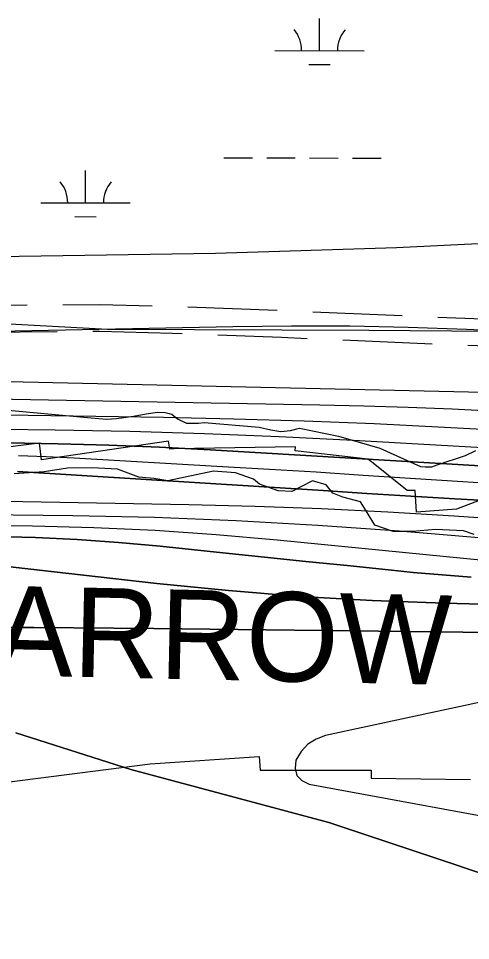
# Model space of a CAD drawing. Extents: x 3219052 to 3256913, y 800770 to 826146.
# Drawn here: x 3230665 to 3231171, y 817204 to 818235 of the extents above; entities that cross this region are included whole.
import ezdxf

# ---------------------------------------------------------------- set-up
doc = ezdxf.new("R2010")
doc.units = 0
for name, color, linetype in [('V-RIVR-EDGE', 7, 'Continuous'), ('V-ROAD-CNTR', 7, 'Continuous'), ('V-RRAP-RVMT', 7, 'Continuous'), ('V-RRAP-RVMT-IDEN', 7, 'Continuous'), ('V-SITE-VEGE', 7, 'Continuous'), ('V-TOPO-DPTH', 7, 'Continuous'), ('V-TOPO-MAJR', 7, 'Continuous'), ('V-TOPO-MINR', 7, 'Continuous'), ('V-TOPO-WATR', 7, 'Continuous'), ('V-WETL-SWMP', 7, 'Continuous')]:
    doc.layers.add(name, color=color, linetype=linetype)

msp = doc.modelspace()

# ---------------------------------------------------------------- linework, layer by layer
at = {"layer": 'V-RIVR-EDGE'}
msp.add_lwpolyline([(3231174.7, 817657.9), (3231162.6, 817661.9), (3231131.3, 817663.3), (3231105.6, 817661.1), (3231083.9, 817661.2), (3231063.5, 817668.2), (3231053.9, 817684.3), (3231047.5, 817694.3), (3231027.5, 817699.6), (3231016.6, 817704), (3231008.8, 817713.5), (3230993.6, 817717.9), (3230970.5, 817705.8), (3230955.3, 817706.7), (3230934.5, 817714.2), (3230927.5, 817719.8), (3230907.6, 817726.8), (3230882.8, 817728.6), (3230831.9, 817717.9), (3230816.3, 817720.5), (3230799.3, 817721.9), (3230775.4, 817731.1), (3230747.2, 817732.5), (3230719.4, 817732.1), (3230693.3, 817727.8), (3230659.8, 817725.7)], dxfattribs=at)
at = {"layer": 'V-ROAD-CNTR'}
for p, q in [((3230954.2, 817908.4), (3230854.2, 817912)), ((3231094, 817902.3), (3230994.1, 817906.7)), ((3231233.9, 817897), (3231134, 817900.6)), ((3231127.6, 817870.8), (3231027.7, 817875.2))]:
    msp.add_line(p, q, dxfattribs=at)
for points in [[(3230674.3, 817914.3), (3230625.8, 817914), (3230574.3, 817915.9)], [(3230814.3, 817913.3), (3230755.6, 817914.8), (3230714.3, 817914.5)], [(3230585.8, 817897.4), (3230764.2, 817887.5), (3231056.9, 817886.3), (3231334.5, 817884.2), (3231463.1, 817879.2), (3231574.9, 817868.7), (3231737.2, 817863.7), (3231809.8, 817860.7), (3231876.6, 817848.6), (3231928.6, 817844.9), (3231999.5, 817846.5), (3232100, 817847.1), (3232247.3, 817862.1)], [(3230707.9, 817884.5), (3230625.3, 817884), (3230607.9, 817884.6)], [(3230847.9, 817882.3), (3230837.1, 817882.7), (3230755.3, 817884.8), (3230747.9, 817884.8)], [(3230987.8, 817876.9), (3230958.9, 817878.2), (3230887.8, 817880.8)], [(3231267.5, 817865.4), (3231261, 817866), (3231167.6, 817869.3)]]:
    msp.add_lwpolyline(points, dxfattribs=at)
at = {"layer": 'V-RRAP-RVMT'}
for points in [[(3230838.7, 817753.6), (3230834.2, 817753.3), (3230832.5, 817762.2), (3230690.4, 817741.2), (3230688.1, 817759.9), (3230631.6, 817752.8), (3230631.4, 817756.7), (3230542.5, 817770.8), (3230540.4, 817762.9), (3230428.9, 817767.3), (3230427.6, 817772.6), (3230297.1, 817753.7), (3230295.9, 817762.3), (3230155.1, 817747.8), (3230155.7, 817741.9), (3230083.5, 817714.2)], [(3231109.9, 817682.7), (3231108.6, 817707), (3231099.5, 817706.9), (3231056.1, 817742.2), (3230974.2, 817751.3), (3230974.5, 817755.9), (3230838.7, 817753.6)], [(3232165.3, 817719.6), (3232052.4, 817690.3), (3232049.5, 817700.3), (3231980.9, 817683.5), (3231976.7, 817687.4), (3231906.8, 817683.8), (3231878.5, 817676.5), (3231876.3, 817681.2), (3231770.8, 817693.1), (3231760.5, 817688.7), (3231757.8, 817692.6), (3231630.9, 817713.5), (3231629.3, 817716.7), (3231617.5, 817713.7), (3231616, 817717.7), (3231480.4, 817738.6), (3231472, 817736.5), (3231470.7, 817739.2), (3231344.7, 817733.2), (3231342, 817738.9), (3231213.9, 817703.1), (3231211.6, 817707.9), (3231154.7, 817686.3), (3231109.9, 817682.7)], [(3230557.8, 817369), (3230812, 817401.2)], [(3230812, 817401.2), (3230933.9, 817409.6), (3230935, 817394.3), (3231059.4, 817394.2), (3231059.5, 817385.2), (3231170.6, 817383.9)]]:
    msp.add_lwpolyline(points, dxfattribs=at)
at = {"layer": 'V-SITE-VEGE'}
for p, q in [((3230613.9, 817800.7), (3230745.9, 817788.2)), ((3230807.6, 817792.7), (3230820.4, 817794.6)), ((3230820.4, 817794.6), (3230828.8, 817794.5)), ((3230828.8, 817794.5), (3230836.4, 817792.3)), ((3230745.9, 817788.2), (3230763, 817787)), ((3230763, 817787), (3230774.5, 817787.6)), ((3230774.5, 817787.6), (3230793.3, 817790.3)), ((3230793.3, 817790.3), (3230807.6, 817792.7)), ((3230836.4, 817792.3), (3230842.5, 817787.1)), ((3230842.5, 817787.1), (3230852.5, 817782.3)), ((3230852.5, 817782.3), (3230866, 817782.5)), ((3230866, 817782.5), (3230872.4, 817783.3)), ((3230872.4, 817783.3), (3230934.1, 817777.8)), ((3230934.1, 817777.8), (3230947.2, 817774.9)), ((3230947.2, 817774.9), (3230958.2, 817773)), ((3230958.2, 817773), (3230969, 817774.1)), ((3230969, 817774.1), (3230979.2, 817776.7)), ((3230979.2, 817776.7), (3231022.6, 817767.9)), ((3231022.6, 817767.9), (3231069.2, 817754.5)), ((3231069.2, 817754.5), (3231114.6, 817734)), ((3231165, 817746.2), (3231176.6, 817751.9)), ((3231133.1, 817735.8), (3231165, 817746.2)), ((3231114.6, 817734), (3231119.6, 817733.4)), ((3231119.6, 817733.4), (3231127.1, 817733.7)), ((3231127.1, 817733.7), (3231133.1, 817735.8))]:
    msp.add_line(p, q, dxfattribs=at)
at = {"layer": 'V-TOPO-DPTH'}
for points in [[(3230652.5, 817760.4), (3230709.1, 817759.4), (3230765.8, 817757.9), (3230822.4, 817755.5), (3230879, 817752.5), (3231288.3, 817728.2), (3231293.9, 817727.8), (3231299.4, 817727.5), (3231304.9, 817727.2), (3231310.5, 817726.9), (3231316, 817726.6), (3231321.6, 817726.4), (3231327.1, 817726.2), (3231332.6, 817726.1), (3231981, 817713.4), (3232007.9, 817713), (3232034.7, 817713), (3232061.6, 817713.4), (3232088.5, 817714.1), (3232573.7, 817730.8)], [(3230663.4, 817728.5), (3231005.5, 817707), (3231054.6, 817703.9), (3231103.7, 817700.9), (3231152.8, 817697.9), (3231201.9, 817695)], [(3231201.9, 817695), (3231152.8, 817697.9), (3231103.7, 817700.9), (3231054.6, 817703.9), (3231005.5, 817707), (3230663.4, 817728.5)], [(3232144.2, 817648.9), (3232056.2, 817644.3), (3232044.7, 817643.8), (3232033.3, 817643.4), (3232021.8, 817643.1), (3232010.3, 817642.9), (3231604.1, 817637.7), (3231553.6, 817637.4), (3231503, 817637.6), (3231452.5, 817638.6), (3231402, 817640.1), (3231382, 817640.9), (3231341.5, 817642.7), (3231301, 817644.8), (3231260.5, 817647.5), (3231220, 817650.6), (3231090.8, 817661.4), (3230999.6, 817668), (3230908.3, 817673.3), (3230817, 817676.7), (3230725.5, 817678.7), (3230592, 817680.3)], [(3232144.2, 817648.9), (3232056.2, 817644.3), (3232044.7, 817643.8), (3232033.3, 817643.4), (3232021.8, 817643.1), (3232010.3, 817642.9), (3231604.1, 817637.7), (3231553.6, 817637.4), (3231503, 817637.6), (3231452.5, 817638.6), (3231402, 817640.1), (3231382, 817640.9), (3231341.5, 817642.7), (3231301, 817644.8), (3231260.5, 817647.5), (3231220, 817650.6), (3231090.8, 817661.4), (3230999.6, 817668), (3230908.3, 817673.3), (3230817, 817676.7), (3230725.5, 817678.7), (3230592, 817680.3)], [(3230637, 817655.7), (3230683.6, 817654.5), (3230730.2, 817652.4), (3230776.7, 817649), (3230823.2, 817644.8), (3230893.5, 817637.4), (3230939.8, 817632.6), (3230986.1, 817627.8), (3231032.4, 817623.1), (3231078.6, 817618.3), (3231106.3, 817615.5), (3231138.8, 817612.6), (3231171.3, 817610.1)], [(3230637, 817655.7), (3230683.6, 817654.5), (3230730.2, 817652.4), (3230776.7, 817649), (3230823.2, 817644.8), (3230893.5, 817637.4), (3230939.8, 817632.6), (3230986.1, 817627.8), (3231032.4, 817623.1), (3231078.6, 817618.3), (3231106.3, 817615.5), (3231138.8, 817612.6), (3231171.3, 817610.1)], [(3232532.2, 817627.7), (3232109.1, 817594.8), (3232070.6, 817592.1), (3232032.1, 817589.6), (3231993.5, 817587.5), (3231954.9, 817585.7), (3231938.7, 817585), (3231891.9, 817583.3), (3231845.2, 817581.9), (3231798.4, 817581), (3231751.7, 817580.4), (3231350.5, 817577.1), (3231326.3, 817577), (3231302.1, 817577.1), (3231277.9, 817577.4), (3231253.7, 817577.9), (3231140.9, 817580.9), (3231060.4, 817584), (3230979.9, 817588.6), (3230899.6, 817595.2), (3230819.4, 817603.1), (3230576.3, 817630.5)], [(3230576.3, 817630.5), (3230819.4, 817603.1), (3230899.6, 817595.2), (3230979.9, 817588.6), (3231060.4, 817584), (3231140.9, 817580.9), (3231253.7, 817577.9), (3231277.9, 817577.4), (3231302.1, 817577.1), (3231326.3, 817577), (3231350.5, 817577.1), (3231751.7, 817580.4), (3231798.4, 817581), (3231845.2, 817581.9), (3231891.9, 817583.3), (3231938.7, 817585), (3231954.9, 817585.7), (3231993.5, 817587.5), (3232032.1, 817589.6), (3232070.6, 817592.1), (3232109.1, 817594.8), (3232532.2, 817627.7)], [(3232117.6, 817554.2), (3232046.1, 817551.8), (3232038.7, 817551.6), (3232031.3, 817551.4), (3232023.9, 817551.3), (3232016.5, 817551.2), (3231882.9, 817550.3), (3231808.7, 817549.9), (3231734.5, 817549.4), (3231660.3, 817549), (3231586.1, 817548.6), (3231380.7, 817547.5), (3231341.7, 817547.4), (3231302.6, 817547.4), (3231263.6, 817547.6), (3231224.6, 817548), (3230816.1, 817552.6), (3230771.4, 817553.1), (3230726.7, 817553.5), (3230682, 817553.7), (3230637.4, 817553.9)], [(3230637.4, 817553.9), (3230682, 817553.7), (3230726.7, 817553.5), (3230771.4, 817553.1), (3230816.1, 817552.6), (3231224.6, 817548), (3231263.6, 817547.6), (3231302.6, 817547.4), (3231341.7, 817547.4), (3231380.7, 817547.5), (3231586.1, 817548.6), (3231660.3, 817549), (3231734.5, 817549.4), (3231808.7, 817549.9), (3231882.9, 817550.3), (3232016.5, 817551.2), (3232023.9, 817551.3), (3232031.3, 817551.4), (3232038.7, 817551.6), (3232046.1, 817551.8), (3232117.6, 817554.2)], [(3230661.5, 817435.9), (3230790.5, 817395.1), (3231011.8, 817335.7), (3231308.3, 817236.8), (3231331.5, 817235), (3231354.8, 817233.4), (3231378, 817232), (3231401.3, 817230.8), (3231424.6, 817229.8), (3231447.9, 817229), (3231968, 817212.1), (3231996, 817211.2), (3232023.9, 817210.3), (3232051.9, 817209.5), (3232079.8, 817208.8), (3232271.6, 817203.6)], [(3232271.6, 817203.6), (3232079.8, 817208.8), (3232051.9, 817209.5), (3232023.9, 817210.3), (3231996, 817211.2), (3231968, 817212.1), (3231447.9, 817229), (3231424.6, 817229.8), (3231401.3, 817230.8), (3231378, 817232), (3231354.8, 817233.4), (3231331.5, 817235), (3231308.3, 817236.8), (3231011.8, 817335.7), (3230790.5, 817395.1), (3230661.5, 817435.9)]]:
    msp.add_lwpolyline(points, dxfattribs=at)
at = {"layer": 'V-TOPO-MAJR'}
for points in [[(3232140.7, 817751.4), (3232053.8, 817748.4), (3232044.7, 817748.1), (3232035.5, 817748), (3232026.3, 817748.1), (3232017.2, 817748.2), (3231924.9, 817750.7), (3231869.6, 817752.6), (3231814.3, 817754.9), (3231759.1, 817758), (3231703.9, 817761.6), (3231363.6, 817785.9), (3231330.9, 817788.1), (3231298.3, 817790.2), (3231265.6, 817792.1), (3231232.9, 817793.9), (3231199.5, 817795.6), (3231150, 817797.9), (3231100.6, 817799.9), (3231051.2, 817801.4), (3231001.7, 817802.5), (3230616.8, 817809.6)], [(3231234, 817481.3), (3231008.2, 817433), (3230997.6, 817428.9), (3230988.3, 817423.3), (3230981, 817415.1), (3230975.2, 817405.3), (3230974.4, 817396.1), (3230976.1, 817388.3), (3230981.7, 817382.7), (3230989.9, 817378.4), (3231271.7, 817326.7)]]:
    msp.add_lwpolyline(points, dxfattribs=at)
at = {"layer": 'V-TOPO-MINR'}
for points in [[(3232232.9, 817846.1), (3232057.3, 817846.3), (3232047.4, 817846.4), (3232037.6, 817846.5), (3232027.8, 817846.7), (3232017.9, 817847), (3231927.3, 817850.1), (3231872.2, 817852.1), (3231817.1, 817854.3), (3231762, 817856.9), (3231706.9, 817859.6), (3231352.8, 817878.3), (3231324.7, 817879.8), (3231296.6, 817881.2), (3231268.5, 817882.5), (3231240.5, 817883.8), (3231166, 817887.1), (3231100.7, 817889.4), (3231035.3, 817890.8), (3230970, 817891), (3230904.6, 817890.3), (3230585.5, 817883.9)], [(3232110.3, 817762), (3232091.7, 817761.5), (3232073, 817760.9), (3232042.3, 817759.8), (3232039, 817759.7), (3232035.7, 817759.6), (3232032.5, 817759.7), (3232029.2, 817759.7), (3231997.4, 817760.7), (3231978.3, 817761.4), (3231959.1, 817762.2), (3231940, 817763.4), (3231920.8, 817764.7), (3231335.4, 817809.3), (3231316.6, 817810.7), (3231297.9, 817811.9), (3231279.1, 817813), (3231260.3, 817814), (3231241.5, 817814.8), (3231222.7, 817815.5), (3231203.9, 817816.1), (3231185.1, 817816.6), (3230536.6, 817831.2)], [(3232208.9, 817742), (3232065.4, 817737), (3232050.3, 817736.6), (3232035.2, 817736.4), (3232020.2, 817736.4), (3232005.1, 817736.7), (3231842.5, 817740.7), (3231751.8, 817743.5), (3231661.1, 817747.1), (3231570.4, 817751.8), (3231479.8, 817757.2), (3231342.7, 817766.3), (3231320.7, 817767.7), (3231298.6, 817769), (3231276.6, 817770.3), (3231254.6, 817771.6), (3231141.5, 817777.7), (3231062.8, 817781.5), (3230984.2, 817784.7), (3230905.5, 817787), (3230826.8, 817788.7), (3230599.5, 817792.1)], [(3232365.5, 817735.5), (3232076.9, 817725.6), (3232056, 817725), (3232035, 817724.7), (3232014, 817724.8), (3231993, 817725), (3231596.9, 817733.9), (3231547.2, 817735.3), (3231497.6, 817737), (3231447.9, 817739.4), (3231398.3, 817742.1), (3231322.1, 817746.7), (3231310.5, 817747.4), (3231299, 817748.1), (3231287.5, 817748.8), (3231276, 817749.5), (3231039.7, 817763), (3230956.3, 817767.2), (3230872.8, 817770.6), (3230789.2, 817773), (3230705.7, 817774.6), (3230583.7, 817776.1)], [(3232573.7, 817730.8), (3232088.5, 817714.1), (3232061.6, 817713.4), (3232034.7, 817713), (3232007.9, 817713), (3231981, 817713.4), (3231332.6, 817726.1), (3231327.1, 817726.2), (3231321.6, 817726.4), (3231316, 817726.6), (3231310.5, 817726.9), (3231304.9, 817727.2), (3231299.4, 817727.5), (3231293.9, 817727.8), (3231288.3, 817728.2), (3230879, 817752.5), (3230822.4, 817755.5), (3230765.8, 817757.9), (3230709.1, 817759.4), (3230652.5, 817760.4)], [(3231184.9, 817715.3), (3231161.9, 817716.7), (3231102.8, 817720.6), (3231050.4, 817724), (3230997.9, 817727.4), (3230945.4, 817730.5), (3230892.8, 817733.6), (3230726.9, 817743.2), (3230695.7, 817744.7), (3230664.5, 817746)], [(3232125.1, 817658), (3232094.6, 817656.7), (3232045.9, 817654.2), (3232039.7, 817654), (3232033.5, 817653.7), (3232027.3, 817653.6), (3232021, 817653.5), (3231900.4, 817652.4), (3231833.9, 817652.2), (3231767.4, 817652.7), (3231700.9, 817654), (3231634.4, 817656), (3231357.4, 817666), (3231329, 817667.2), (3231300.5, 817668.5), (3231272, 817670.2), (3231243.6, 817672), (3231152.2, 817678.3), (3231078, 817682.8), (3231003.8, 817686.6), (3230929.6, 817689.2), (3230855.3, 817691.1), (3230607.3, 817695.6)], [(3232144.2, 817648.9), (3232056.2, 817644.3), (3232044.7, 817643.8), (3232033.3, 817643.4), (3232021.8, 817643.1), (3232010.3, 817642.9), (3231604.1, 817637.7), (3231553.6, 817637.4), (3231503, 817637.6), (3231452.5, 817638.6), (3231402, 817640.1), (3231382, 817640.9), (3231341.5, 817642.7), (3231301, 817644.8), (3231260.5, 817647.5), (3231220, 817650.6), (3231090.8, 817661.4), (3230999.6, 817668), (3230908.3, 817673.3), (3230817, 817676.7), (3230725.5, 817678.7), (3230592, 817680.3)], [(3231189.1, 817628.4), (3230954.2, 817651.7), (3230885.9, 817657.6), (3230817.5, 817662.4), (3230748.9, 817665.3), (3230680.4, 817667.1), (3230580.5, 817668.4)], [(3231171.3, 817610.1), (3231138.8, 817612.6), (3231106.3, 817615.5), (3231078.6, 817618.3), (3231032.4, 817623.1), (3230986.1, 817627.8), (3230939.8, 817632.6), (3230893.5, 817637.4), (3230823.2, 817644.8), (3230776.7, 817649), (3230730.2, 817652.4), (3230683.6, 817654.5), (3230637, 817655.7)], [(3232532.2, 817627.7), (3232109.1, 817594.8), (3232070.6, 817592.1), (3232032.1, 817589.6), (3231993.5, 817587.5), (3231954.9, 817585.7), (3231938.7, 817585), (3231891.9, 817583.3), (3231845.2, 817581.9), (3231798.4, 817581), (3231751.7, 817580.4), (3231350.5, 817577.1), (3231326.3, 817577), (3231302.1, 817577.1), (3231277.9, 817577.4), (3231253.7, 817577.9), (3231140.9, 817580.9), (3231060.4, 817584), (3230979.9, 817588.6), (3230899.6, 817595.2), (3230819.4, 817603.1), (3230576.3, 817630.5)], [(3232117.6, 817554.2), (3232046.1, 817551.8), (3232038.7, 817551.6), (3232031.3, 817551.4), (3232023.9, 817551.3), (3232016.5, 817551.2), (3231882.9, 817550.3), (3231808.7, 817549.9), (3231734.5, 817549.4), (3231660.3, 817549), (3231586.1, 817548.6), (3231380.7, 817547.5), (3231341.7, 817547.4), (3231302.6, 817547.4), (3231263.6, 817547.6), (3231224.6, 817548), (3230816.1, 817552.6), (3230771.4, 817553.1), (3230726.7, 817553.5), (3230682, 817553.7), (3230637.4, 817553.9)], [(3230661.5, 817435.9), (3230790.5, 817395.1), (3231011.8, 817335.7), (3231308.3, 817236.8), (3231331.5, 817235), (3231354.8, 817233.4), (3231378, 817232), (3231401.3, 817230.8), (3231424.6, 817229.8), (3231447.9, 817229), (3231968, 817212.1), (3231996, 817211.2), (3232023.9, 817210.3), (3232051.9, 817209.5), (3232079.8, 817208.8), (3232271.6, 817203.6)]]:
    msp.add_lwpolyline(points, dxfattribs=at)
at = {"layer": 'V-TOPO-WATR'}
msp.add_lwpolyline([(3231201.9, 817695), (3231152.8, 817697.9), (3231103.7, 817700.9), (3231054.6, 817703.9), (3231005.5, 817707), (3230663.4, 817728.5)], dxfattribs=at)
at = {"layer": 'V-WETL-SWMP'}
for p, q in [((3231001.5, 818199.2), (3231001.6, 818235.2)), ((3230951.5, 818199.3), (3231051.5, 818199.1)), ((3230989.5, 818183.8), (3231013.5, 818183.7)), ((3230894.4, 818079.3), (3230926.4, 818079.3)), ((3230942.4, 818079.2), (3230974.4, 818079.1)), ((3230990.4, 818079.1), (3231022.4, 818079)), ((3231038.4, 818079), (3231070.4, 818078.9)), ((3230739.7, 818028.9), (3230739.8, 818064.9)), ((3230689.7, 818029), (3230789.7, 818028.8)), ((3230727.7, 818013.5), (3230751.7, 818013.4)), ((3231087.7, 817979), (3231292.2, 817988.9)), ((3230885.1, 817972.6), (3231087.7, 817979)), ((3230639.6, 817968.7), (3230885.1, 817972.6))]:
    msp.add_line(p, q, dxfattribs=at)
for centre, start, end in [((3230946.3, 818199.8), 359.1081, 40.6518), ((3231056.8, 818199.5), 139.1081, 180.6517), ((3230684.5, 818029.5), 359.1081, 40.6518), ((3230795, 818029.3), 139.1081, 180.6517)]:
    msp.add_arc(centre, 35.2, start, end, dxfattribs=at)

# ---------------------------------------------------------------- texts
at = {"layer": 'V-RRAP-RVMT-IDEN'}
msp.add_text('ARROW', height=100, rotation=358.7529, dxfattribs=at).set_placement((3230635.8, 817500.7))

doc.saveas('drawing.dxf')
